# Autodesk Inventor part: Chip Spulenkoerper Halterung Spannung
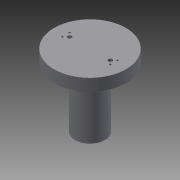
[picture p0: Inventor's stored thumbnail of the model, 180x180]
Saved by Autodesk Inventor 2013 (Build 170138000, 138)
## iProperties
Created: 2013-02
Part Number: Chip Spulenkoerper Halterung Spannung
Material: Allgemein
Document SubType Name: Modeling
Designer: Hübner
Density: 1 g/cm^3
Author: Hübner
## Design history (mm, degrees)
sketch "Skizze1"
  geometry: C1 r 30 at (0, 0); 1 further point
  constraints: 1 centre point, 1 coincident
  dimensions: "d0" = 60 diameter of C1
extrude "Extrusion1" new body sketch "Skizze1" distance "d1" = 10; taper "d2" = 0 deg
sketch "Skizze2"
  geometry: C1 r 30 at (0, 0) reference; C2 r 12.5 at (0, 0)
  constraints: 1 centre point, 1 coincident
  dimensions: "d3" = 25 diameter of C2
extrude "Extrusion2" join sketch "Skizze2" distance "d4" = 50; taper "d5" = 0 deg
sketch "Skizze3"
  geometry: L1 (-17, 0)-(17, 0); C1 r 30 at (0, 0) reference; 1 further point
  constraints: 2 end point, 1 coincident, 1 horizontal, 1 midpoint
  dimensions: "d7" = 34 distance of L1.end L1.start
hole "Bohrung1" sketch "Skizze3" at (-17, 0), (17, 0) diameter "d9" = 3.242; stored, may be unused: countersink angle "d13" = 90 deg, drill point angle "d15" = 118 deg; dims "d10" = 6, "d11" = 4, "d12" = 2, "d14" = 6
sketch "Skizze4"
  geometry: L1 (-20, 3)-(20, 3); L2 (20, 3)-(20, -3); L3 (20, -3)-(-20, -3); L4 (-20, -3)-(-20, 3); C1 r 30 at (0, 0) reference; 2 further points
  constraints: 8 end point, 2 midpoint, 2 parallel, 1 horizontal, 1 horizontal alignment, 1 perpendicular, 1 vertical alignment
  dimensions: "d16" = 40 distance of L2.end L3.end; "d17" = 6 distance of L1.end L2.end
hole "Bohrung2" sketch "Skizze4" at (-20, 3), (-20, -3), (20, 3), (20, -3) diameter "d18" = 1.5; stored, may be unused: countersink angle "d22" = 90 deg, drill point angle "d24" = 118 deg; dims "d19" = 6, "d20" = 4, "d21" = 2, "d23" = 8
node "Volumenkörper1"
